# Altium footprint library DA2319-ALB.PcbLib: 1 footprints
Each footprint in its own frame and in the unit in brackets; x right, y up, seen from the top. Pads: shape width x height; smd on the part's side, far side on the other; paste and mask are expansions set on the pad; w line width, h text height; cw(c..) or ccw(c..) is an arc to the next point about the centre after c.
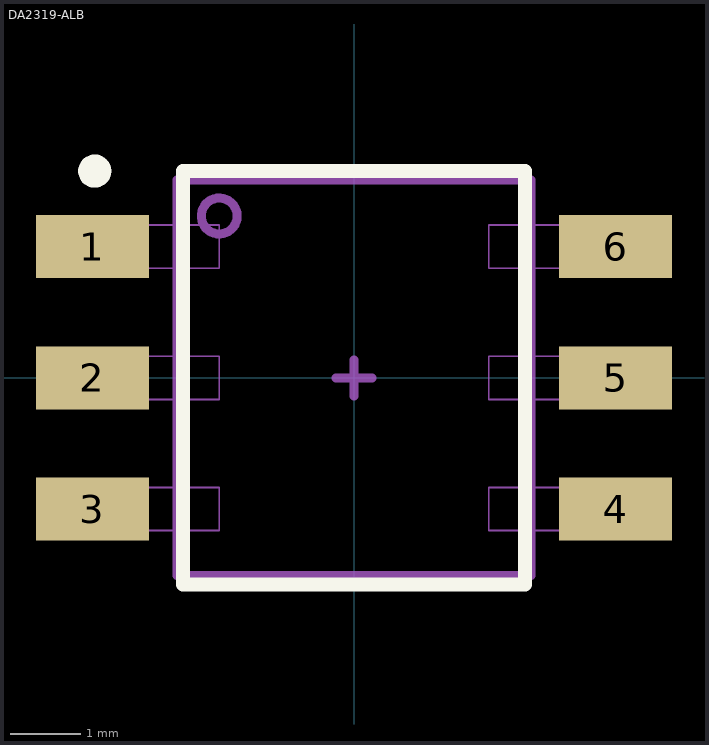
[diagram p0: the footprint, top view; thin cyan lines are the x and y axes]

## DA2319-ALB [mil] "Gate Transformer"
height 213
pads (6):
  rect 63x35 smd: 1(-145.5,73) 2(-145.5,0) 3(-145.5,-73) 4(145.5,-73) 5(145.5,0) 6(145.5,73)
Top Overlay:
  circle w10: c-144.24,115 r4.24
  lines w7.78: -95,-115 -95,115 95,115 95,-115 -95,-115
M5 Assembly Top:
  circle w5: c-75,90 r10
  lines w1: -161.5,-73 -145.5,-73 ; -161.5,-73 -161.5,-61 -139.5,-61 -139.5,-73 ; -161.5,-73 -161.5,-85 -139.5,-85 -139.5,-73 ; -161.5,0 -145.5,0 ; -161.5,0 -161.5,12 -139.5,12 -139.5,0 ; -161.5,0 -161.5,-12 -139.5,-12 -139.5,0 ; -161.5,73 -161.5,61 -139.5,61 -139.5,73 ; -161.5,73 -161.5,85 -139.5,85 -139.5,73 ; -161.5,73 -145.5,73 ; -145.5,-85 -145.5,-73 ; -145.5,-85 -75,-85 -75,-61 -145.5,-61 ; -145.5,-85 -145.5,-73 ; -145.5,-73 -145.5,-61 ; -145.5,-73 -139.5,-73 ; -145.5,-73 -145.5,-61 ; -145.5,-12 -145.5,0 ; -145.5,-12 -75,-12 -75,12 -145.5,12 ; -145.5,-12 -145.5,0 ; -145.5,0 -145.5,12 ; -145.5,0 -139.5,0 ; -145.5,0 -145.5,12 ; -145.5,61 -145.5,73 ; -145.5,61 -75,61 -75,85 -145.5,85 ; -145.5,61 -145.5,73 ; -145.5,73 -145.5,85 ; -145.5,73 -139.5,73 ; -145.5,73 -145.5,85 ; 139.5,-73 145.5,-73 ; 139.5,-73 139.5,-61 161.5,-61 161.5,-73 ; 139.5,-73 139.5,-85 161.5,-85 161.5,-73 ; 139.5,0 145.5,0 ; 139.5,0 139.5,12 161.5,12 161.5,0 ; 139.5,0 139.5,-12 161.5,-12 161.5,0 ; 139.5,73 145.5,73 ; 139.5,73 139.5,85 161.5,85 161.5,73 ; 139.5,73 139.5,61 161.5,61 161.5,73 ; 145.5,-85 145.5,-73 ; 145.5,-85 75,-85 75,-61 145.5,-61 ; 145.5,-85 145.5,-73 ; 145.5,-73 145.5,-61 ; 145.5,-73 161.5,-73 ; 145.5,-73 145.5,-61 ; 145.5,-12 145.5,0 ; 145.5,-12 75,-12 75,12 145.5,12 ; 145.5,-12 145.5,0 ; 145.5,0 145.5,12 ; 145.5,0 161.5,0 ; 145.5,0 145.5,12 ; 145.5,61 145.5,73 ; 145.5,61 75,61 75,85 145.5,85 ; 145.5,61 145.5,73 ; 145.5,73 145.5,85 ; 145.5,73 161.5,73 ; 145.5,73 145.5,85
  lines w5: -98.5,-110 98.5,-110 98.5,110 -98.5,110 -98.5,-110
  text ".Designator" at -177,-10 h40
M15  Courtyards Top:
  lines w5: -10,0 0,0 ; 0,-10 0,0 ; 0,10 0,0 ; 10,0 0,0
3D body: height 50, standoff 5, extent -98.5,-110 -55,110
3D body: height 213, standoff 212, extent -98.5,-110 98.5,110
3D body: height 10, standoff 0, extent 139.5,61 161.5,85
3D body: height 40, standoff 30, extent 75,61 139.5,85
3D body: height 40, standoff 10, extent 139.5,61 145.5,85
3D body: height 10, standoff 0, extent 139.5,-12 161.5,12
3D body: height 40, standoff 30, extent 75,-12 139.5,12
3D body: height 40, standoff 10, extent 139.5,-12 145.5,12
3D body: height 10, standoff 0, extent 139.5,-85 161.5,-61
3D body: height 40, standoff 30, extent 75,-85 139.5,-61
3D body: height 40, standoff 10, extent 139.5,-85 145.5,-61
3D body: height 10, standoff 0, extent -161.5,-85 -139.5,-61
3D body: height 40, standoff 30, extent -139.5,-85 -75,-61
3D body: height 40, standoff 10, extent -145.5,-85 -139.5,-61
3D body: height 10, standoff 0, extent -161.5,-12 -139.5,12
3D body: height 40, standoff 30, extent -139.5,-12 -75,12
3D body: height 40, standoff 10, extent -145.5,-12 -139.5,12
3D body: height 40, standoff 10, extent -145.5,61 -139.5,85
3D body: height 40, standoff 30, extent -139.5,61 -75,85
3D body: height 10, standoff 0, extent -161.5,61 -139.5,85
3D body: height 212, standoff 50, extent -98.5,-110 98.5,110
3D body: height 50, standoff 5, extent 55,-110 98.5,110
3D body: height 149.86, standoff 10.14, extent -69.72,-100 69.72,100
3D body: height 213.1, standoff 213, extent -84.92,80.02 -65,99.98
